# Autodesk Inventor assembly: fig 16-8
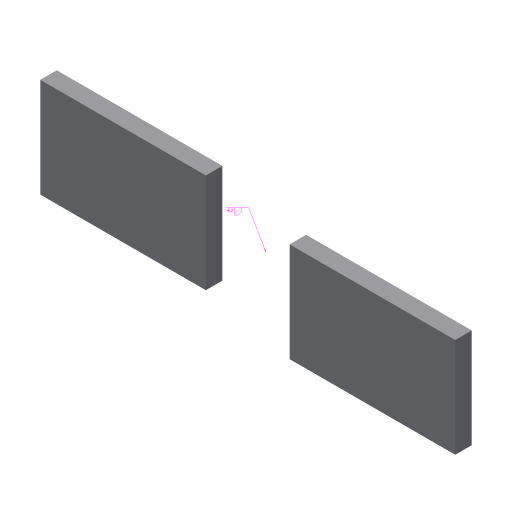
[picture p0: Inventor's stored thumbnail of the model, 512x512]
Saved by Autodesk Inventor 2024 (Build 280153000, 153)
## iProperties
Created: 2004-07
Part Number: fig 16-8
Document SubType Name: Weldment
Designer: CADCIM Technologies
Manufacturer: Standard
Standards Organization: Custom
Author: CADCIM Technologies
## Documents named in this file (2)
- D:\PROJECTS\Project 2023\RESOURCES INVENTOR 2024\RESOURCES INVENTOR 2024\Inventor_2023_Part\Inventor_2024_Part\c16_Inv_2024_prt\fig 16-8\fig 16-8.iam
- D:\PROJECTS\Project 2023\RESOURCES INVENTOR 2024\RESOURCES INVENTOR 2024\Inventor_2023_Part\Inventor_2024_Part\c16_Inv_2024_prt\fig 16-8\Plate.ipt
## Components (2 placed, 1 different names)
1. Plate:1 — Mate:1, Flush:1, Flush:2
2. Plate:2 — Mate:1, Flush:1, Flush:2
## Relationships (3: Flush 2, Mate 1)
- Mate:1: Plate:1 ↔ Plate:2
- Flush:1: Plate:1 ↔ Plate:2
- Flush:2: Plate:1 ↔ Plate:2
